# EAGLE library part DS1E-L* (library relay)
DS-RELAYS HIGHLY SENSITIVE 1500 V FCC SURGE NAiS WITHSTANDING MINIATURE RELAY Source: http://www.mew-europe.com/.. en_ds_61005_0001.pdf
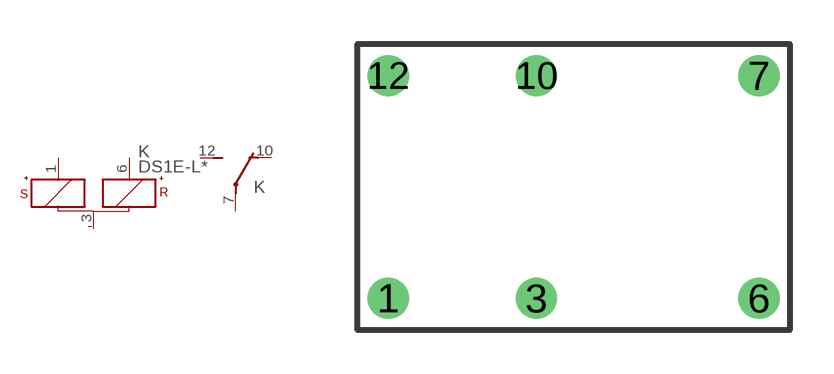
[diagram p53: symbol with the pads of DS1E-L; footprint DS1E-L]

Designator prefix K; gates 2=U 1=+KS+KR-

## DS1E-L1.5V (OC_FARNELL: unknown; OC_NEWARK: unknown), DS1E-L3V (OC_FARNELL: unknown; OC_NEWARK: unknown), DS1E-L5V (MF: AROMAT/ MATSUSHITA; MPN: DS1E-SL-DC5V; OC_FARNELL: unknown; OC_NEWARK: 10C5701), DS1E-L6V (OC_FARNELL: unknown; OC_NEWARK: unknown), DS1E-L9V (OC_FARNELL: unknown; OC_NEWARK: unknown), DS1E-L12V (MPN: DS1E-SL-DC12V; OC_FARNELL: unknown; OC_NEWARK: 13P3222), DS1E-L24V (OC_FARNELL: unknown; OC_NEWARK: unknown), DS1E-L48V (MF: AROMAT/ MATSUSHITA; MPN: DS1E-SL-DC48V; OC_FARNELL: unknown; OC_NEWARK: 10C5700)  [DS1E-L]
1  1:S+  pas
3  1:-  pas
6  1:R+  pas
7  2:P  pas
10  2:O  pas
12  2:S  pas

## Footprint DS1E-L (pad centres in mm)
DS-RELAYS HIGHLY SENSITIVE 1500 V FCC SURGE NAiS WITHSTANDING MINIATURE RELAY Source: http://www.mew-europe.com/.. en_ds_61005_0001.pdf
drill 0.9 round: 1 -6.35,-3.81; 3 -1.27,-3.81; 6 6.35,-3.81; 7 6.35,3.81; 10 -1.27,3.81; 12 -6.35,3.81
